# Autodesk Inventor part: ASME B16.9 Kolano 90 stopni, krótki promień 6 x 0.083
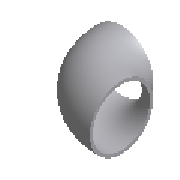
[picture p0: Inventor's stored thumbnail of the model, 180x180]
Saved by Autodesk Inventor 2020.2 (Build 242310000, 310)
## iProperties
Manager: www.cadconsulting.pl
Company: Fabian Stasiak CAD Consulting
IsCustomPart: 0
NAME: PIPING: ASME B16.9 Short Radius 90 Deg Elbow
DATA: <meta><inlinegroups number="0" deflen="0"></inlinegroups><connections number="2"></connections><angles><a>1.57079632679489</a></angles></meta>
Created: 2014-02
Part Number: ASME B16.9 Kolano 90 stopni, krótki promień 6 x 0.083
Material: Stal kuta
Description: Element kuty, spawany doczołowo - Kolano 90º o krótkim promieniu .calowe
Document SubType Name: Modeling
Standard: ASME B16.9
Designer: F.Stasiak
Standard Revision: 2003
Standards Organization: ANSI
Language: pl-PL
Size Designation: 6 x 0.083
Categories: <MemberInstance><Categories><Category DisplayName="Rury cienko- i grubościenne" InternalName="4347fa0f-2144-441d-94cd-e3e15c92b736" Mnemonic="TUBEANDPIPE"><Cate
Density: 1 g/cm^3
Appearance: Stal
Catalog Web Link: www.expertbooks.pl
Author: F.Stasiak
Subject: Zbiór ćwiczeń. Autodesk Inventor 2020. Kurs Professional
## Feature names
1. Sweep1
## Parameters: d0 = 163.9316 mm, d1 = 168.148 mm, OD = 168.148 mm, A = 152.4 mm, d2 = 152.4 mm, d3 = 152.4 mm, d4 = 0, T = 2.1082 mm, d5 = 0, Size_Designation = 12.345 mm
